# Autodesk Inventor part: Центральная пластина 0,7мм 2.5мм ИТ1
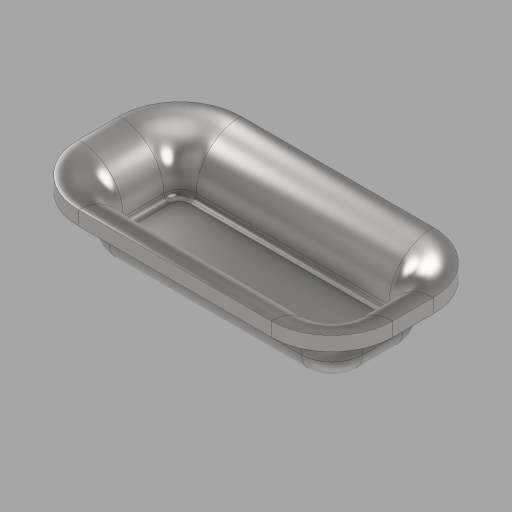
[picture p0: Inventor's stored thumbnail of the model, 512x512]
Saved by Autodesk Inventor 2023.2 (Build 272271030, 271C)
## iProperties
Created: 2025-02
Part Number: Центральная пластина 0,7мм 2.5мм ИТ1
Material: Типовые
Document SubType Name: Modeling
Designer: Артур
Density: 1 g/cm^3
Appearance: По умолчанию
Author: Артур
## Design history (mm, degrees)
sketch "Эскиз1"
  geometry: L1 (-4.75, 2.5)-(4.75, 2.5); L2 (6.25, 1)-(6.25, -1); L3 (4.75, -2.5)-(-4.75, -2.5); L4 (-6.25, -1)-(-6.25, 1); L5 (-6.25, 2.5)-(6.25, -2.5); L6 (6.25, 2.5)-(-6.25, -2.5); L7 (4.75, 4)-(-4.75, 4); L8 (-7.75, 1)-(-7.75, -1); L9 (-4.75, -4)-(4.75, -4); L10 (7.75, -1)-(7.75, 1); A1 r 1.5 centre (4.75, 1) between (6.25, 1) and (4.75, 2.5); A2 r 1.5 centre (4.75, -1) between (4.75, -2.5) and (6.25, -1); A3 r 1.5 centre (-4.75, -1) between (-6.25, -1) and (-4.75, -2.5); A4 r 1.5 centre (-4.75, 1) between (-4.75, 2.5) and (-6.25, 1); A5 r 3 centre (-4.75, 1) between (-4.75, 4) and (-7.75, 1); A6 r 3 centre (-4.75, -1) between (-7.75, -1) and (-4.75, -4); A7 r 3 centre (4.75, -1) between (4.75, -4) and (7.75, -1); A8 r 3 centre (4.75, 1) between (7.75, 1) and (4.75, 4); 1 further point
  constraints: 20 end point, 16 point on circle, 8 centre point, 8 point on line, 8 tangent, 4 parallel, 3 equal radius, 2 midpoint, 2 perpendicular, 1 horizontal, 7 other
  dimensions: "d0" = 12.5 distance of L5.end L6.end; "d1" = 5 distance of L6.start L5.end; "d2" = 1.5 radius of A1; "d3" = 1.5 radial gap between concentric circles of A1 A8
extrude "Выдавливание1" new body sketch "Эскиз1" distance "d4" = 0.7; taper "d5" = 0 deg
extrude "Выдавливание2" join sketch "Эскиз1" distance "d6" = 2.5; taper "d7" = 0 deg
fillet "Сопряжение1" dims "d8" = 1.5
fillet "Сопряжение2" dims "d9" = 1
feature "Удаление грани1"
feature "Удаление грани2"
feature "Толщина1" dims "d10" = 0.7
node "Твердое тело1"
